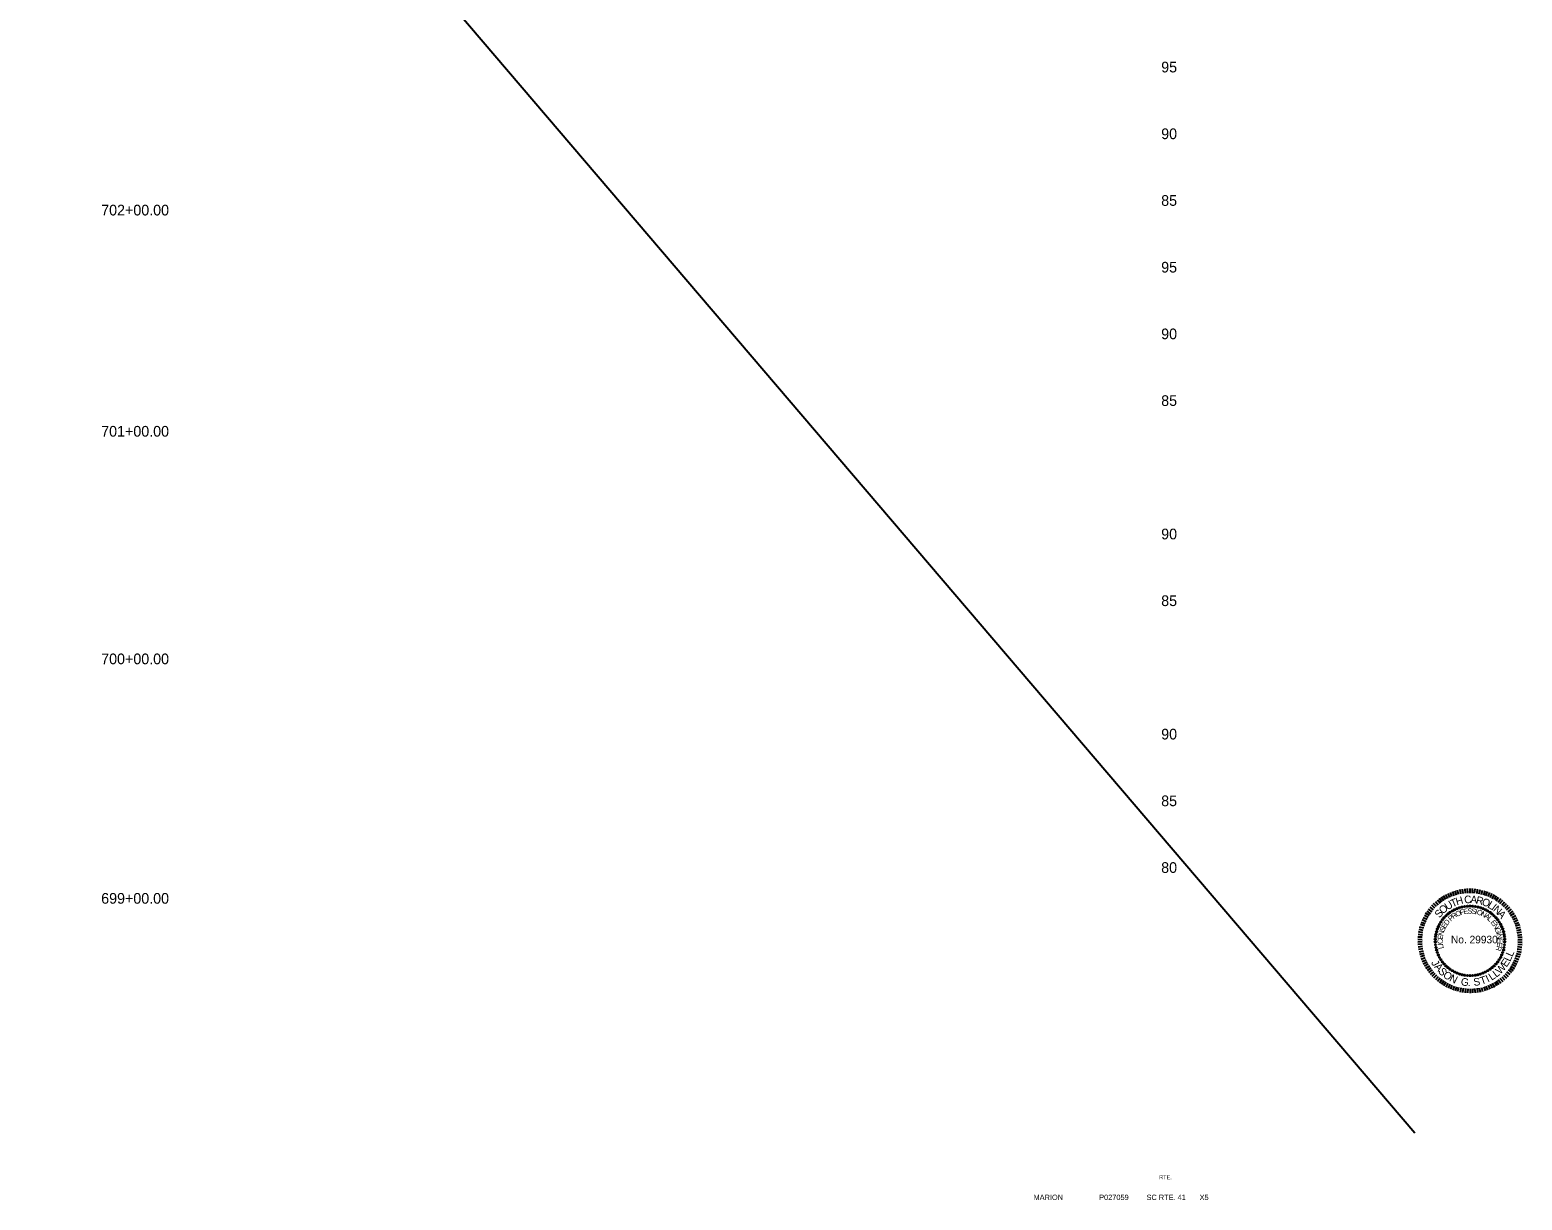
# Model space of a CAD drawing. Extents: x 952 to 1206, y 942 to 2399.
# Drawn here: x 1072.1 to 1184, y 2135.5 to 2223.2 of the extents above; entities that cross this region are included whole.
import ezdxf

# ---------------------------------------------------------------- set-up
doc = ezdxf.new("R2010")
doc.units = 0
for name, color, linetype in [('Default', 7, 'Continuous'), ('RD_SHT_TX', 7, 'Continuous'), ('RD_TX_PEShield', 7, 'Continuous'), ('RD_XS_TX_Elev_EX', 7, 'Continuous'), ('RD_XS_TX_Station', 7, 'Continuous')]:
    doc.layers.add(name, color=color, linetype=linetype)

# ---------------------------------------------------------------- blocks, each defined once
blk = doc.blocks.new('STILLWELL')
at = {"layer": 'RD_TX_PEShield'}
for p, q in [((-16.7, 30.8), (-18.2, 33.7)), ((-15.1, 31.6), (-16.5, 34.6)), ((-13.6, 32.3), (-14.8, 35.3)), ((-11.9, 32.9), (-13, 36)), ((-10.3, 33.4), (-11.2, 36.6)), ((-8.6, 33.9), (-9.4, 37.1)), ((-6.9, 34.3), (-7.5, 37.5)), ((-5.2, 34.6), (-5.7, 37.8)), ((-3.5, 34.8), (-3.8, 38)), ((-1.8, 34.9), (-1.9, 38.2)), ((0, 34.9), (0, 38.2)), ((1.7, 34.9), (1.9, 38.2)), ((3.4, 34.8), (3.7, 38)), ((5.2, 34.6), (5.6, 37.8)), ((6.9, 34.3), (7.5, 37.5)), ((8.6, 33.9), (9.3, 37.1)), ((10.2, 33.4), (11.2, 36.6)), ((11.9, 32.9), (13, 36)), ((13.5, 32.3), (14.7, 35.3)), ((15.1, 31.6), (16.5, 34.6)), ((16.6, 30.8), (18.2, 33.7)), ((-28.5, 20.9), (-31.1, 22.8)), ((-27.4, 22.2), (-29.9, 24.3)), ((-26.3, 23.5), (-28.7, 25.7)), ((-25.1, 24.7), (-27.4, 27.1)), ((-23.8, 25.9), (-26, 28.4)), ((-22.5, 27), (-24.5, 29.6)), ((-21.1, 28.1), (-23, 30.7)), ((-19.7, 29.1), (-21.5, 31.8)), ((-18.2, 30), (-19.9, 32.8)), ((18.2, 30), (19.8, 32.8)), ((19.6, 29.1), (21.4, 31.8)), ((21.1, 28.1), (23, 30.7)), ((22.4, 27), (24.5, 29.6)), ((23.8, 25.9), (25.9, 28.4)), ((25, 24.7), (27.3, 27.1)), ((26.2, 23.5), (28.6, 25.7)), ((27.4, 22.2), (29.9, 24.3)), ((28.5, 20.9), (31.1, 22.8)), ((-33.6, 11.8), (-36.6, 12.9)), ((-32.9, 13.4), (-35.9, 14.7)), ((-32.2, 15), (-35.1, 16.4)), ((-31.4, 16.5), (-34.2, 18.1)), ((-30.5, 18), (-33.3, 19.7)), ((-29.5, 19.4), (-32.2, 21.3)), ((29.5, 19.4), (32.2, 21.3)), ((30.4, 18), (33.2, 19.7)), ((31.3, 16.5), (34.2, 18.1)), ((32.1, 15), (35.1, 16.4)), ((32.9, 13.4), (35.9, 14.7)), ((33.5, 11.8), (36.6, 12.9)), ((-35.9, -0.1), (-39.2, 0)), ((-35.8, 1.7), (-39.1, 1.9)), ((-35.6, 3.4), (-38.9, 3.8)), ((-35.4, 5.1), (-38.6, 5.7)), ((-35.1, 6.8), (-38.2, 7.5)), ((-34.6, 8.5), (-37.8, 9.4)), ((-34.1, 10.2), (-37.2, 11.2)), ((34.1, 10.2), (37.2, 11.2)), ((34.6, 8.5), (37.7, 9.4)), ((35, 6.8), (38.2, 7.5)), ((35.3, 5.1), (38.5, 5.7)), ((35.6, 3.4), (38.8, 3.8)), ((35.7, 1.7), (39, 1.9)), ((35.8, -0.1), (39.1, 0)), ((-35.9, -1.8), (-39.2, -1.9)), ((-35.8, -3.5), (-39.1, -3.8)), ((-35.6, -5.3), (-38.9, -5.6)), ((-35.4, -7), (-38.6, -7.5)), ((-35.1, -8.7), (-38.2, -9.4)), ((-34.6, -10.4), (-37.8, -11.2)), ((34.6, -10.4), (37.7, -11.2)), ((35, -8.7), (38.2, -9.4)), ((35.3, -7), (38.5, -7.5)), ((35.6, -5.3), (38.8, -5.6)), ((35.7, -3.5), (39, -3.8)), ((35.8, -1.8), (39.1, -1.9)), ((-34.1, -12), (-37.2, -13)), ((-33.6, -13.6), (-36.6, -14.8)), ((-32.9, -15.3), (-35.9, -16.6)), ((-32.2, -16.8), (-35.1, -18.3)), ((-31.4, -18.4), (-34.2, -19.9)), ((-30.5, -19.9), (-33.3, -21.6)), ((-29.5, -21.3), (-32.2, -23.2)), ((29.5, -21.3), (32.2, -23.2)), ((30.4, -19.9), (33.2, -21.6)), ((31.3, -18.4), (34.2, -19.9)), ((32.1, -16.8), (35.1, -18.3)), ((32.9, -15.3), (35.9, -16.6)), ((33.5, -13.6), (36.6, -14.8)), ((34.1, -12), (37.2, -13)), ((-28.5, -22.7), (-31.1, -24.7)), ((-27.4, -24.1), (-29.9, -26.2)), ((-26.3, -25.4), (-28.7, -27.6)), ((-25.1, -26.6), (-27.4, -28.9)), ((-23.8, -27.8), (-26, -30.2)), ((-22.5, -28.9), (-24.5, -31.4)), ((-21.1, -29.9), (-23, -32.6)), ((-19.7, -30.9), (-21.5, -33.7)), ((-18.2, -31.8), (-19.9, -34.7)), ((-16.7, -32.7), (-18.2, -35.6)), ((-15.1, -33.5), (-16.5, -36.4)), ((15.1, -33.5), (16.5, -36.4)), ((16.6, -32.7), (18.2, -35.6)), ((18.2, -31.8), (19.8, -34.7)), ((19.6, -30.9), (21.4, -33.7)), ((21.1, -29.9), (23, -32.6)), ((22.4, -28.9), (24.5, -31.4)), ((23.8, -27.8), (25.9, -30.2)), ((25, -26.6), (27.3, -28.9)), ((26.2, -25.4), (28.6, -27.6)), ((27.4, -24.1), (29.9, -26.2)), ((28.5, -22.7), (31.1, -24.7)), ((-13.6, -34.1), (-14.8, -37.2)), ((-11.9, -34.8), (-13, -37.8)), ((-10.3, -35.3), (-11.2, -38.4)), ((-8.6, -35.8), (-9.4, -38.9)), ((-6.9, -36.1), (-7.5, -39.3)), ((-5.2, -36.4), (-5.7, -39.7)), ((-3.5, -36.6), (-3.8, -39.9)), ((-1.8, -36.8), (-1.9, -40)), ((0, -36.8), (0, -40.1)), ((1.7, -36.8), (1.9, -40)), ((3.4, -36.6), (3.7, -39.9)), ((5.2, -36.4), (5.6, -39.7)), ((6.9, -36.1), (7.5, -39.3)), ((8.6, -35.8), (9.3, -38.9)), ((10.2, -35.3), (11.2, -38.4)), ((11.9, -34.8), (13, -37.8)), ((13.5, -34.1), (14.7, -37.2))]:
    blk.add_line(p, q, dxfattribs=at)
for centre in [(-11.6, 22.4), (-9.8, 23.2), (-7.9, 23.9), (-6, 24.4), (-4, 24.8), (-2, 25), (0, 25.1), (2, 25), (3.9, 24.8), (5.9, 24.4), (7.8, 23.9), (9.7, 23.2), (11.5, 22.4), (-22.9, 11.5), (-21.9, 13.2), (-20.7, 14.9), (-19.5, 16.4), (-18.1, 17.8), (-16.6, 19.2), (-15, 20.4), (-13.3, 21.5), (13.3, 21.5), (15, 20.4), (16.5, 19.2), (18, 17.8), (19.4, 16.4), (20.7, 14.9), (21.8, 13.2), (22.9, 11.5), (-26.1, 0.1), (-25.9, 2.1), (-25.6, 4), (-25.1, 6), (-24.5, 7.9), (-23.8, 9.7), (23.7, 9.7), (24.5, 7.9), (25.1, 6), (25.5, 4), (25.8, 2.1), (26, 0.1), (-26.1, -1.9), (-25.9, -3.9), (-25.6, -5.9), (-25.1, -7.8), (-24.5, -9.7), (-23.8, -11.6), (23.7, -11.6), (24.5, -9.7), (25.1, -7.8), (25.5, -5.9), (25.8, -3.9), (26, -1.9), (-22.9, -13.4), (-21.9, -15.1), (-20.7, -16.7), (-19.5, -18.3), (-18.1, -19.7), (-16.6, -21), (-15, -22.2), (15, -22.2), (16.5, -21), (18, -19.7), (19.4, -18.3), (20.7, -16.7), (21.8, -15.1), (22.9, -13.4), (-13.3, -23.3), (-11.6, -24.3), (-9.8, -25.1), (-7.9, -25.8), (-6, -26.3), (-4, -26.7), (-2, -26.9), (0, -27), (2, -26.9), (3.9, -26.7), (5.9, -26.3), (7.8, -25.8), (9.7, -25.1), (11.5, -24.3), (13.3, -23.3)]:
    blk.add_circle(centre, 0.49, dxfattribs=at)
for s, height, rotation, p in [('S', 5.68, 49.6435, (-22.9, 15.8)), ('O', 5.68, 41.5972, (-20.4, 18.8)), ('U', 5.68, 32.2152, (-16.9, 21.8)), ('T', 5.68, 23.5044, (-13.2, 24.1)), ('H', 5.68, 16.1357, (-9.9, 25.6)), ('F', 3.92, 15.9995, (-7.1, 18.3)), ('E', 3.92, 8.9511, (-4.7, 19)), ('C', 5.68, 4.076, (-4.2, 27.1)), ('S', 3.92, 1.2546, (-1.9, 19.4)), ('A', 5.68, 355.3651, (0.1, 27.4)), ('S', 3.92, 353.558, (0.8, 19.5)), ('I', 3.92, 345.8615, (3.5, 19.2)), ('R', 5.68, 347.3188, (4.1, 27.1)), ('O', 3.92, 342.6583, (4.7, 19)), ('O', 5.68, 338.6079, (8.3, 26.2)), ('L', 5.68, 329.226, (12.6, 24.4)), ('I', 5.68, 322.5218, (15.5, 22.8)), ('N', 5.68, 319.1729, (16.8, 21.8)), ('E', 3.92, 60.2341, (-18.5, 7.9)), ('D', 3.92, 52.5376, (-17.1, 10.3)), ('P', 3.92, 41.0022, (-14.5, 13.5)), ('R', 3.92, 33.3057, (-12.5, 15.3)), ('O', 3.92, 24.9735, (-10, 16.9)), ('N', 3.92, 333.6842, (7.7, 18)), ('A', 3.92, 325.3521, (10.4, 16.7)), ('L', 3.92, 317.6555, (12.6, 15.1)), ('E', 3.92, 308.0396, (15.1, 12.8)), ('N', 3.92, 300.343, (16.8, 10.6)), ('A', 5.68, 310.4621, (20.1, 19)), ('C', 3.92, 92.2915, (-20.4, -3.2)), ('E', 3.92, 83.9594, (-20.5, -0.2)), ('N', 3.92, 76.2628, (-20.2, 2.5)), ('S', 3.92, 67.9307, (-19.5, 5.4)), ('G', 3.92, 292.0109, (18.3, 8.1)), ('I', 3.92, 283.0368, (19.5, 5.1)), ('N', 3.92, 279.8336, (19.8, 4)), ('E', 3.92, 271.5014, (20.3, 1.1)), ('I', 3.92, 95.4947, (-20.2, -4.3)), ('L', 3.92, 101.9075, (-19.7, -6.6)), ('R', 3.92, 256.1083, (20.1, -4.4)), ('E', 3.92, 263.8049, (20.4, -1.7)), ('L', 5.68, 65.098, (31.6, -13.3)), ('J', 5.68, 299.033, (-29.4, -17.3)), ('A', 5.68, 310.5887, (-27.2, -20.6)), ('S', 5.68, 310.5887, (-24.3, -24)), ('W', 5.68, 47.0518, (22.6, -26.4)), ('E', 5.68, 56.4327, (27.3, -21.1)), ('L', 5.68, 65.098, (30, -16.9)), ('O', 5.68, 321.0072, (-20.8, -27.4)), ('N', 5.68, 333.4326, (-16, -30.8)), ('G', 5.68, 352.2045, (-7.2, -34.2)), ('S', 5.68, 8.0826, (2.9, -34.8)), ('T', 5.68, 18.9019, (8.5, -33.9)), ('I', 5.68, 25.3991, (13.3, -32.2)), ('L', 5.68, 34.0644, (16.2, -30.9)), ('L', 5.68, 37.6708, (19.6, -28.7)), ('.', 5.68, 0.8698, (-1.8, -34.9))]:
    blk.add_text(s, height=height, rotation=rotation, dxfattribs=at).set_placement(p)
blk.add_text('No. 29930', height=5.68, dxfattribs=at).set_placement((-14.3, -2.8))

msp = doc.modelspace()

# ---------------------------------------------------------------- linework, layer by layer
at = {"layer": 'RD_SHT_TX'}
msp.add_line((966.94, 2385.17), (1175.94, 2140.52), dxfattribs=at)

# ---------------------------------------------------------------- block references
at = {"layer": 'Default', "xscale": 0.1, "yscale": 0.10000000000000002}
msp.add_blockref('STILLWELL', (1180.08, 2155), dxfattribs=at)

# ---------------------------------------------------------------- texts
at = {"layer": 'RD_SHT_TX'}
for s, height, p in [('RTE.', 0.3, (1156.77, 2137.03)), ('MARION', 0.4, (1147.35, 2135.48)), ('P027059', 0.4, (1152.27, 2135.48)), ('SC RTE. 41', 0.4, (1155.82, 2135.48)), ('X5', 0.4, (1159.8, 2135.48))]:
    msp.add_text(s, height=height, dxfattribs=at).set_placement(p)
at = {"layer": 'RD_XS_TX_Elev_EX'}
for s, p in [('95', (1156.92, 2220)), ('90', (1156.92, 2215)), ('85', (1156.92, 2210)), ('95', (1156.92, 2205)), ('90', (1156.92, 2200)), ('85', (1156.92, 2195)), ('90', (1156.92, 2185)), ('85', (1156.92, 2180)), ('90', (1156.92, 2170)), ('85', (1156.92, 2165)), ('80', (1156.92, 2160))]:
    msp.add_text(s, height=0.8, dxfattribs=at).set_placement(p)
at = {"layer": 'RD_XS_TX_Station'}
for s, p in [('702+00.00', (1077.44, 2209.28)), ('701+00.00', (1077.44, 2192.7)), ('700+00.00', (1077.44, 2175.64)), ('699+00.00', (1077.44, 2157.69))]:
    msp.add_text(s, height=0.8, dxfattribs=at).set_placement(p)

doc.saveas('drawing.dxf')
